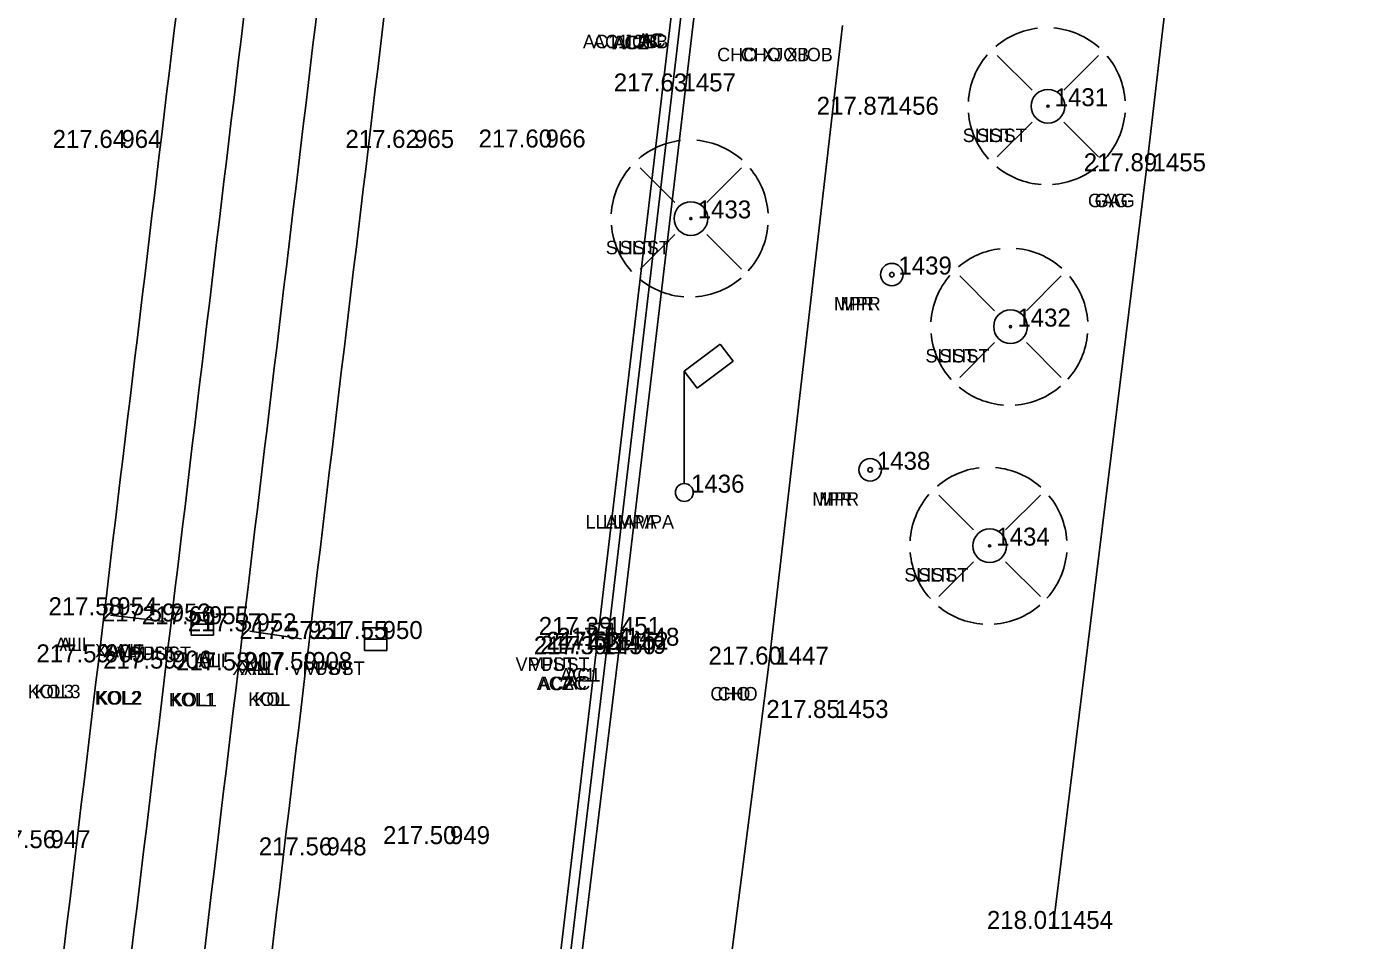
# Model space of a CAD drawing. Extents: x -471047 to -470889, y -1102859 to -1102000.
# Drawn here: x -470982.59 to -470952.73, y -1102585.27 to -1102564.92 of the extents above; entities that cross this region are included whole.
import ezdxf

# ---------------------------------------------------------------- set-up
doc = ezdxf.new("R2010")
doc.units = 0
for name, color, linetype in [('Vrstva 1', 7, 'Continuous'), ('Vrstva 16', 7, 'Continuous'), ('Vrstva 23', 7, 'Continuous'), ('Vrstva 24', 7, 'Continuous'), ('Vrstva 25', 7, 'Continuous'), ('Vrstva 29', 7, 'Continuous'), ('Vrstva 34', 7, 'Continuous'), ('Vrstva 35', 7, 'Continuous'), ('Vrstva 36', 7, 'Continuous'), ('Vrstva 38', 7, 'Continuous'), ('Vrstva 5', 7, 'Continuous'), ('Vrstva 6', 7, 'Continuous'), ('Vrstva 7', 7, 'Continuous'), ('Vrstva 8', 7, 'Continuous')]:
    doc.layers.add(name, color=color, linetype=linetype)

msp = doc.modelspace()

# ---------------------------------------------------------------- linework, layer by layer
at = {"layer": 'Vrstva 1'}
for points in [[(-471040.344, -1102858.385), (-471031.676, -1102846.187), (-471026.357, -1102838.629), (-471023.212, -1102833.975), (-471019.21, -1102827.465), (-471016.861, -1102823.272), (-471013.099, -1102815.912), (-471010.824, -1102810.955), (-471007.329, -1102802.292), (-471005.34, -1102796.515), (-471002.842, -1102787.838), (-471001.3, -1102780.997), (-471000.19, -1102774.713), (-470999.247, -1102768.204), (-470998.794, -1102764.784), (-470997.199, -1102751.812), (-470994.899, -1102732.807), (-470992.551, -1102713.262), (-470990.326, -1102694.887), (-470988.122, -1102676.57), (-470985.812, -1102657.305), (-470983.537, -1102638.407), (-470981.386, -1102620.622), (-470979.843, -1102608.014), (-470976.377, -1102579.253), (-470972.945, -1102550.69), (-470970.475, -1102530.206), (-470967.905, -1102508.801), (-470965.053, -1102485.131), (-470962.734, -1102465.9), (-470960.173, -1102444.812), (-470957.795, -1102425.103), (-470954.965, -1102401.839), (-470953.834, -1102392.574), (-470952.33, -1102379.985), (-470950.744, -1102366.853), (-470948.978, -1102352.106), (-470947.037, -1102335.844), (-470944.949, -1102318.462), (-470944.013, -1102310.745), (-470942.39, -1102297.267), (-470939.519, -1102273.45), (-470937.593, -1102257.43), (-470936.064, -1102244.81), (-470934.114, -1102228.634), (-470931.621, -1102207.856), (-470929.536, -1102190.857), (-470926.572, -1102166.31), (-470924.91, -1102152.663), (-470923.413, -1102140.333), (-470921.923, -1102127.669), (-470921.155, -1102120.084), (-470920.446, -1102109.574), (-470919.912, -1102099.137), (-470919.63, -1102088.981), (-470919.523, -1102081.193), (-470919.563, -1102070.395), (-470919.714, -1102064.236), (-470920.134, -1102054.704), (-470920.462, -1102047.615), (-470920.599, -1102044.52), (-470920.743, -1102041.873), (-470921.125, -1102034.455), (-470921.774, -1102030.337), (-470922.418, -1102027.787), (-470923.734, -1102023.93), (-470924.872, -1102021.434), (-470926.752, -1102018.182), (-470927.953, -1102016.45), (-470929.616, -1102014.424), (-470932.252, -1102011.756), (-470935.111, -1102009.425), (-470938.391, -1102007.371), (-470942.651, -1102005.401)], [(-471041.328, -1102857.18), (-471032.144, -1102844.242), (-471027.583, -1102837.763), (-471024.388, -1102833.028), (-471020.451, -1102826.6), (-471018.089, -1102822.378), (-471014.542, -1102815.445), (-471012.233, -1102810.418), (-471009.247, -1102803.108), (-471006.795, -1102796.098), (-471004.315, -1102787.532), (-471002.782, -1102780.723), (-471001.674, -1102774.458), (-471000.75, -1102768.095), (-471000.28, -1102764.601), (-470998.692, -1102751.741), (-470996.378, -1102732.635), (-470994.028, -1102713.058), (-470991.808, -1102694.749), (-470989.616, -1102676.447), (-470987.284, -1102657.013), (-470985.031, -1102638.272), (-470982.87, -1102620.431), (-470981.334, -1102607.933), (-470977.881, -1102579.263), (-470974.429, -1102550.492), (-470971.964, -1102530.054), (-470969.391, -1102508.607), (-470966.54, -1102484.984), (-470964.231, -1102465.853), (-470961.679, -1102444.752), (-470959.304, -1102425.078), (-470956.455, -1102401.634), (-470955.339, -1102392.489), (-470953.812, -1102379.71), (-470952.249, -1102366.808), (-470950.479, -1102352.023), (-470948.536, -1102335.868), (-470946.426, -1102318.233), (-470945.493, -1102310.531), (-470943.864, -1102297.013), (-470940.984, -1102273.071), (-470939.078, -1102257.195), (-470937.559, -1102244.684), (-470935.592, -1102228.353), (-470933.101, -1102207.653), (-470931.011, -1102190.57), (-470928.046, -1102166.021), (-470926.409, -1102152.578), (-470924.898, -1102140.121), (-470923.427, -1102127.544), (-470922.647, -1102119.826), (-470921.919, -1102109.229), (-470921.42, -1102099.134), (-470921.127, -1102089.016), (-470921.023, -1102081.453), (-470921.061, -1102070.468), (-470921.209, -1102064.314), (-470921.666, -1102053.966), (-470922.156, -1102043.345), (-470922.299, -1102039.934), (-470922.637, -1102034.36), (-470923.091, -1102031.241), (-470923.847, -1102028.247), (-470925.083, -1102024.594), (-470926.222, -1102022.086), (-470928.04, -1102018.943), (-470929.138, -1102017.357), (-470930.929, -1102015.175), (-470933.062, -1102013.049), (-470936.379, -1102010.368), (-470939.169, -1102008.662), (-470942.899, -1102006.906), (-470945.661, -1102005.908)], [(-471043.557, -1102855.955), (-471035.129, -1102844.026), (-471029.872, -1102836.499), (-471026.577, -1102831.578), (-471022.675, -1102825.415), (-471020.123, -1102821.053), (-471016.667, -1102814.59), (-471014.208, -1102809.45), (-471011.177, -1102802.451), (-471008.55, -1102795.333), (-471006.082, -1102787.209), (-471004.464, -1102780.376), (-471003.265, -1102774.167), (-471002.327, -1102767.948), (-471001.636, -1102762.527), (-471000.297, -1102751.605), (-470997.959, -1102732.524), (-470995.602, -1102712.802), (-470993.412, -1102694.623), (-470991.21, -1102676.17), (-470988.891, -1102656.857), (-470986.625, -1102638.083), (-470984.455, -1102620.195), (-470982.936, -1102607.733), (-470979.497, -1102579.223), (-470976.023, -1102550.279), (-470973.554, -1102529.822), (-470970.991, -1102508.497), (-470968.146, -1102484.787), (-470965.835, -1102465.72), (-470963.284, -1102444.529), (-470960.91, -1102424.942), (-470958.043, -1102401.343), (-470956.946, -1102392.356), (-470955.396, -1102379.408), (-470953.851, -1102366.636), (-470952.049, -1102351.733), (-470950.124, -1102335.611), (-470948.034, -1102318.083), (-470947.094, -1102310.328), (-470945.421, -1102296.51), (-470942.58, -1102272.848), (-470940.675, -1102256.948), (-470939.176, -1102244.526), (-470937.187, -1102228.174), (-470934.708, -1102207.467), (-470932.621, -1102190.433), (-470929.634, -1102165.778), (-470928.004, -1102152.415), (-470926.45, -1102139.595), (-470925.003, -1102127.418), (-470924.249, -1102119.695), (-470923.515, -1102109.093), (-470923.018, -1102099.069), (-470922.711, -1102088.911), (-470922.643, -1102081.356), (-470922.797, -1102070.414), (-470923.018, -1102064.454), (-470923.52, -1102053.203), (-470923.823, -1102047.529), (-470924.123, -1102041.506), (-470924.462, -1102037.486), (-470924.934, -1102031.904), (-470925.664, -1102028.672), (-470926.771, -1102025.506), (-470927.959, -1102022.914), (-470929.674, -1102020.028), (-470930.76, -1102018.498), (-470932.447, -1102016.478), (-470935.215, -1102013.816), (-470937.644, -1102011.98), (-470940.381, -1102010.371), (-470943.968, -1102008.669), (-470947.145, -1102007.524), (-470950.874, -1102006.74)], [(-471044.756, -1102855.056), (-471036.376, -1102843.177), (-471031.167, -1102835.741), (-471027.859, -1102830.8), (-471023.934, -1102824.593), (-471021.43, -1102820.312), (-471018.011, -1102813.91), (-471015.536, -1102808.75), (-471012.578, -1102801.897), (-471009.95, -1102794.77), (-471007.561, -1102786.914), (-471005.936, -1102780.074), (-471004.727, -1102773.818), (-471003.828, -1102767.827), (-471003.121, -1102762.345), (-471001.787, -1102751.467), (-470999.446, -1102732.348), (-470997.073, -1102712.539), (-470994.902, -1102694.521), (-470992.696, -1102676.023), (-470990.376, -1102656.68), (-470988.131, -1102638.071), (-470985.947, -1102620.018), (-470984.417, -1102607.512), (-470980.993, -1102579.08), (-470977.514, -1102550.137), (-470975.048, -1102529.649), (-470972.488, -1102508.37), (-470969.618, -1102484.508), (-470967.34, -1102465.669), (-470964.767, -1102444.39), (-470962.402, -1102424.781), (-470959.534, -1102401.193), (-470958.432, -1102392.151), (-470956.883, -1102379.208), (-470955.335, -1102366.424), (-470953.535, -1102351.506), (-470951.606, -1102335.399), (-470949.519, -1102317.94), (-470948.575, -1102310.159), (-470946.889, -1102296.144), (-470944.056, -1102272.618), (-470942.139, -1102256.659), (-470940.657, -1102244.341), (-470938.638, -1102227.749), (-470936.19, -1102207.298), (-470934.102, -1102190.255), (-470931.124, -1102165.639), (-470929.492, -1102152.254), (-470927.915, -1102139.252), (-470926.46, -1102127.103), (-470925.74, -1102119.604), (-470925.012, -1102108.913), (-470924.523, -1102099.054), (-470924.217, -1102088.866), (-470924.148, -1102081.334), (-470924.301, -1102070.391), (-470924.518, -1102064.43), (-470924.97, -1102054.435), (-470925.588, -1102041.569), (-470925.963, -1102035.313), (-470926.405, -1102032.225), (-470927.078, -1102029.198), (-470928.123, -1102026.148), (-470929.318, -1102023.558), (-470930.84, -1102020.97), (-470931.868, -1102019.515), (-470933.443, -1102017.605), (-470936.26, -1102014.885), (-470938.429, -1102013.255), (-470941.213, -1102011.639), (-470944.847, -1102009.927), (-470947.723, -1102008.912), (-470951.444, -1102008.161), (-470954.511, -1102007.931), (-470957.895, -1102008.041)]]:
    msp.add_spline(points, degree=3, dxfattribs=at)
at = {"layer": 'Vrstva 16'}
for p, q in [((-470960.196, -1102566.335), (-470960.972, -1102565.56)), ((-470959.486, -1102566.335), (-470958.712, -1102565.56)), ((-470960.196, -1102567.045), (-470960.972, -1102567.82)), ((-470959.486, -1102567.045), (-470958.712, -1102567.82)), ((-470968.15, -1102568.838), (-470968.926, -1102568.063)), ((-470967.44, -1102568.838), (-470966.666, -1102568.063)), ((-470968.15, -1102569.548), (-470968.926, -1102570.323)), ((-470967.44, -1102569.548), (-470966.666, -1102570.323)), ((-470961.03, -1102571.248), (-470961.806, -1102570.473)), ((-470960.32, -1102571.248), (-470959.546, -1102570.473)), ((-470961.03, -1102571.958), (-470961.806, -1102572.733)), ((-470960.32, -1102571.958), (-470959.546, -1102572.733)), ((-470961.496, -1102576.129), (-470962.27, -1102575.354)), ((-470960.786, -1102576.129), (-470960.01, -1102575.354)), ((-470961.496, -1102576.839), (-470962.27, -1102577.614)), ((-470960.786, -1102576.839), (-470960.01, -1102577.614))]:
    msp.add_line(p, q, dxfattribs=at)
for centre, radius in [((-470959.841, -1102566.69), 0.375), ((-470959.841, -1102566.69), 0.025), ((-470959.841, -1102566.69), 0.025), ((-470967.795, -1102569.193), 0.375), ((-470967.795, -1102569.193), 0.025), ((-470967.795, -1102569.193), 0.025), ((-470960.675, -1102571.603), 0.375), ((-470960.675, -1102571.603), 0.025), ((-470960.675, -1102571.603), 0.025), ((-470961.14, -1102576.484), 0.375), ((-470961.14, -1102576.484), 0.025), ((-470961.14, -1102576.484), 0.025)]:
    msp.add_circle(centre, radius, dxfattribs=at)
for centre, start, end in [((-470959.867, -1102566.69), 96.7144, 130.447), ((-470959.867, -1102566.69), 48.1897, 84.9117), ((-470959.867, -1102566.69), 139.23, 176.4602), ((-470959.867, -1102566.69), 3.8615, 39.6013), ((-470959.867, -1102566.69), 184.9408, 222.2827), ((-470959.867, -1102566.69), 318.1086, 355.0481), ((-470967.821, -1102569.193), 96.7144, 130.447), ((-470967.821, -1102569.193), 48.1897, 84.9117), ((-470967.821, -1102569.193), 139.23, 176.4602), ((-470967.821, -1102569.193), 3.8615, 39.6013), ((-470959.867, -1102566.69), 230.4703, 265.8356), ((-470959.867, -1102566.69), 274.1732, 310.7861), ((-470967.821, -1102569.193), 184.9408, 222.2827), ((-470967.821, -1102569.193), 318.1086, 355.0481), ((-470960.701, -1102571.603), 96.7144, 130.447), ((-470960.701, -1102571.603), 48.1897, 84.9117), ((-470967.821, -1102569.193), 230.4703, 265.8356), ((-470967.821, -1102569.193), 274.1732, 310.7861), ((-470960.701, -1102571.603), 139.23, 176.4602), ((-470960.701, -1102571.603), 3.8615, 39.6013), ((-470960.701, -1102571.603), 184.9408, 222.2827), ((-470960.701, -1102571.603), 318.1086, 355.0481), ((-470960.701, -1102571.603), 230.4703, 265.8356), ((-470960.701, -1102571.603), 274.1732, 310.7861), ((-470961.166, -1102576.484), 96.7144, 130.447), ((-470961.166, -1102576.484), 48.1897, 84.9117), ((-470961.166, -1102576.484), 139.23, 176.4602), ((-470961.166, -1102576.484), 3.8615, 39.6013), ((-470961.166, -1102576.484), 184.9408, 222.2827), ((-470961.166, -1102576.484), 318.1086, 355.0481), ((-470961.166, -1102576.484), 274.1732, 310.7861), ((-470961.166, -1102576.484), 230.4703, 265.8356)]:
    msp.add_arc(centre, 1.75, start, end, dxfattribs=at)
at = {"layer": 'Vrstva 23'}
for p, q in [((-470967.146, -1102571.991), (-470967.941, -1102572.596)), ((-470966.856, -1102572.368), (-470967.146, -1102571.991)), ((-470967.654, -1102572.974), (-470966.856, -1102572.368)), ((-470967.941, -1102572.596), (-470967.941, -1102575.096)), ((-470967.941, -1102572.596), (-470967.654, -1102572.974))]:
    msp.add_line(p, q, dxfattribs=at)
msp.add_circle((-470967.941, -1102575.296), 0.2, dxfattribs=at)
at = {"layer": 'Vrstva 24'}
for centre, radius in [((-470963.319, -1102570.442), 0.25), ((-470963.319, -1102570.442), 0.05), ((-470963.801, -1102574.792), 0.25), ((-470963.801, -1102574.792), 0.05)]:
    msp.add_circle(centre, radius, dxfattribs=at)
at = {"layer": 'Vrstva 25'}
for p, q in [((-470978.929, -1102577.978), (-470978.929, -1102578.478)), ((-470978.429, -1102577.978), (-470978.929, -1102577.978)), ((-470978.429, -1102578.478), (-470978.429, -1102577.978)), ((-470978.929, -1102578.228), (-470978.429, -1102578.228)), ((-470975.064, -1102578.313), (-470975.064, -1102578.813)), ((-470974.564, -1102578.313), (-470975.064, -1102578.313)), ((-470974.564, -1102578.813), (-470974.564, -1102578.313)), ((-470970.051, -1102578.218), (-470970.051, -1102578.718)), ((-470969.551, -1102578.218), (-470970.051, -1102578.218)), ((-470969.551, -1102578.718), (-470969.551, -1102578.218)), ((-470978.929, -1102578.478), (-470978.429, -1102578.478)), ((-470975.064, -1102578.563), (-470974.564, -1102578.563)), ((-470970.051, -1102578.468), (-470969.551, -1102578.468)), ((-470970.051, -1102578.718), (-470969.551, -1102578.718)), ((-470975.064, -1102578.813), (-470974.564, -1102578.813))]:
    msp.add_line(p, q, dxfattribs=at)
at = {"layer": 'Vrstva 29'}
for p, q in [((-470979.525, -1102578.168), (-470980.721, -1102578.028)), ((-470976.472, -1102578.56), (-470977.621, -1102578.388))]:
    msp.add_line(p, q, dxfattribs=at)
at = {"layer": 'Vrstva 34'}
for p, q in [((-470968.13, -1102566.36), (-470968.13, -1102566.36)), ((-470959.84, -1102566.69), (-470959.84, -1102566.69)), ((-470963.61, -1102566.88), (-470963.61, -1102566.88)), ((-470980.63, -1102567.62), (-470980.63, -1102567.62)), ((-470974.11, -1102567.62), (-470974.11, -1102567.62)), ((-470971.18, -1102567.61), (-470971.18, -1102567.61)), ((-470957.66, -1102568.14), (-470957.66, -1102568.14)), ((-470967.79, -1102569.19), (-470967.79, -1102569.19)), ((-470963.32, -1102570.44), (-470963.32, -1102570.44)), ((-470960.67, -1102571.6), (-470960.67, -1102571.6)), ((-470963.8, -1102574.79), (-470963.8, -1102574.79)), ((-470967.94, -1102575.3), (-470967.94, -1102575.3)), ((-470961.14, -1102576.48), (-470961.14, -1102576.48)), ((-470980.72, -1102578.03), (-470980.72, -1102578.03)), ((-470979.53, -1102578.17), (-470979.53, -1102578.17)), ((-470978.68, -1102578.23), (-470978.68, -1102578.23)), ((-470977.62, -1102578.39), (-470977.62, -1102578.39)), ((-470976.47, -1102578.56), (-470976.47, -1102578.56)), ((-470974.81, -1102578.56), (-470974.81, -1102578.56)), ((-470969.8, -1102578.47), (-470969.8, -1102578.47)), ((-470969.39, -1102578.71), (-470969.39, -1102578.71)), ((-470969.91, -1102578.9), (-470969.91, -1102578.9)), ((-470969.68, -1102578.89), (-470969.68, -1102578.89)), ((-470969.63, -1102578.8), (-470969.63, -1102578.8)), ((-470980.99, -1102579.08), (-470980.99, -1102579.08)), ((-470979.5, -1102579.22), (-470979.5, -1102579.22)), ((-470977.88, -1102579.26), (-470977.88, -1102579.26)), ((-470976.38, -1102579.25), (-470976.38, -1102579.25)), ((-470966.06, -1102579.13), (-470966.06, -1102579.13)), ((-470964.73, -1102580.32), (-470964.73, -1102580.32)), ((-470973.31, -1102583.13), (-470973.31, -1102583.13)), ((-470982.21, -1102583.22), (-470982.21, -1102583.22)), ((-470976.06, -1102583.38), (-470976.06, -1102583.38)), ((-470959.73, -1102585.02), (-470959.73, -1102585.02))]:
    msp.add_line(p, q, dxfattribs=at)
at = {"layer": 'Vrstva 5'}
for p, q in [((-470969.913, -1102578.903), (-470968.23, -1102564.623)), ((-470971.196, -1102589.753), (-470969.913, -1102578.903))]:
    msp.add_line(p, q, dxfattribs=at)
at = {"layer": 'Vrstva 6'}
for p, q in [((-470956.273, -1102556.258), (-470957.656, -1102568.144)), ((-470957.656, -1102568.144), (-470959.734, -1102585.018))]:
    msp.add_line(p, q, dxfattribs=at)
at = {"layer": 'Vrstva 7'}
for p, q in [((-470969.386, -1102578.705), (-470967.713, -1102564.6)), ((-470970.734, -1102589.803), (-470969.386, -1102578.705))]:
    msp.add_line(p, q, dxfattribs=at)
at = {"layer": 'Vrstva 8'}
for p, q in [((-470969.682, -1102578.891), (-470968.004, -1102564.574)), ((-470966.057, -1102579.132), (-470964.419, -1102564.89)), ((-470970.974, -1102589.772), (-470969.682, -1102578.891)), ((-470967.658, -1102591.567), (-470966.057, -1102579.132))]:
    msp.add_line(p, q, dxfattribs=at)

# ---------------------------------------------------------------- texts
at = {"layer": 'Vrstva 35'}
for s, p in [('AC1 JOB', (-470970.199, -1102565.4)), ('AC1 JOB', (-470969.974, -1102565.4)), ('AC2', (-470969.546, -1102565.42)), ('AC2', (-470969.505, -1102565.42)), ('AC', (-470968.989, -1102565.37)), ('AC', (-470968.914, -1102565.37)), ('CHO XJOB', (-470967.209, -1102565.69)), ('CHO XJOB', (-470966.684, -1102565.69)), ('SLIST', (-470961.74, -1102567.49)), ('SLIST', (-470961.429, -1102567.49)), ('GAG', (-470958.95, -1102568.94)), ('GAG', (-470958.799, -1102568.94)), ('SLIST', (-470969.69, -1102569.99)), ('SLIST', (-470969.379, -1102569.99)), ('MPR', (-470964.609, -1102571.24)), ('MPR', (-470964.459, -1102571.24)), ('SLIST', (-470962.57, -1102572.4)), ('SLIST', (-470962.259, -1102572.4)), ('MPR', (-470965.089, -1102575.59)), ('MPR', (-470964.939, -1102575.59)), ('LLAMPA', (-470970.14, -1102576.1)), ('LLAMPA', (-470969.754, -1102576.1)), ('SLIST', (-470963.04, -1102577.28)), ('SLIST', (-470962.729, -1102577.28)), ('ALI', (-470981.958, -1102578.83)), ('ALI', (-470981.859, -1102578.83)), ('XALI', (-470981.068, -1102578.97)), ('XALI', (-470980.894, -1102578.97)), ('VPUST', (-470980.58, -1102579.03)), ('VPUST', (-470980.269, -1102579.03)), ('ALI', (-470978.858, -1102579.19)), ('ALI', (-470978.759, -1102579.19)), ('VPUST', (-470971.7, -1102579.27)), ('VPUST', (-470971.389, -1102579.27)), ('XALI', (-470978.008, -1102579.36)), ('XALI', (-470977.834, -1102579.36)), ('VPUST', (-470976.71, -1102579.36)), ('VPUST', (-470976.399, -1102579.36)), ('AC1', (-470970.707, -1102579.51)), ('AC1', (-470970.59, -1102579.51)), ('KOL3', (-470982.565, -1102579.88)), ('KOL3', (-470982.418, -1102579.88)), ('AC2', (-470971.226, -1102579.7)), ('AC2', (-470971.185, -1102579.7)), ('AC', (-470970.669, -1102579.69)), ('AC', (-470970.594, -1102579.69)), ('KOL2', (-470981.075, -1102580.02)), ('KOL2', (-470981.041, -1102580.02)), ('KOL1', (-470979.422, -1102580.06)), ('KOL1', (-470979.38, -1102580.06)), ('KOL', (-470977.655, -1102580.05)), ('KOL', (-470977.519, -1102580.05)), ('CHO', (-470967.361, -1102579.93)), ('CHO', (-470967.199, -1102579.93))]:
    msp.add_text(s, height=0.3, dxfattribs=at).set_placement(p)
at = {"layer": 'Vrstva 36'}
for s, p in [(' 1457', (-470968.13, -1102566.36)), (' 1456', (-470963.61, -1102566.88)), (' 1431', (-470959.84, -1102566.69)), (' 964', (-470980.63, -1102567.62)), (' 965', (-470974.11, -1102567.62)), (' 966', (-470971.18, -1102567.61)), (' 1455', (-470957.66, -1102568.14)), (' 1433', (-470967.79, -1102569.19)), (' 1439', (-470963.32, -1102570.44)), (' 1432', (-470960.67, -1102571.6)), (' 1438', (-470963.8, -1102574.79)), (' 1436', (-470967.94, -1102575.3)), (' 1434', (-470961.14, -1102576.48)), (' 954', (-470980.72, -1102578.03)), (' 953', (-470979.53, -1102578.17)), (' 955', (-470978.68, -1102578.23)), (' 952', (-470977.62, -1102578.39)), (' 1451', (-470969.8, -1102578.47)), (' 951', (-470976.47, -1102578.56)), (' 950', (-470974.81, -1102578.56)), (' 1452', (-470969.63, -1102578.8)), (' 1448', (-470969.39, -1102578.71)), (' 905', (-470980.99, -1102579.08)), (' 1450', (-470969.91, -1102578.9)), (' 1449', (-470969.68, -1102578.89)), (' 906', (-470979.5, -1102579.22)), (' 907', (-470977.88, -1102579.26)), (' 908', (-470976.38, -1102579.25)), (' 1447', (-470966.06, -1102579.13)), (' 1453', (-470964.73, -1102580.32)), (' 947', (-470982.21, -1102583.22)), (' 949', (-470973.31, -1102583.13)), (' 948', (-470976.06, -1102583.38)), (' 1454', (-470959.73, -1102585.02))]:
    msp.add_text(s, height=0.4, dxfattribs=at).set_placement(p)
at = {"layer": 'Vrstva 38'}
for s, p in [('217.63 ', (-470969.513, -1102566.36)), ('217.87 ', (-470964.993, -1102566.88)), ('217.64 ', (-470982.012, -1102567.62)), ('217.62 ', (-470975.491, -1102567.62)), ('217.60 ', (-470972.523, -1102567.61)), ('217.89 ', (-470959.044, -1102568.14)), ('217.58 ', (-470982.104, -1102578.03)), ('217.59 ', (-470980.914, -1102578.17)), ('217.60 ', (-470980.023, -1102578.23)), ('217.57 ', (-470979.003, -1102578.39)), ('217.39 ', (-470971.184, -1102578.47)), ('217.57 ', (-470977.853, -1102578.56)), ('217.55 ', (-470976.194, -1102578.56)), ('217.53 ', (-470971.013, -1102578.8)), ('217.54 ', (-470970.772, -1102578.71)), ('217.59 ', (-470982.374, -1102579.08)), ('217.39 ', (-470971.294, -1102578.9)), ('217.41 ', (-470971.15, -1102578.89)), ('217.60 ', (-470967.403, -1102579.13)), ('217.59 ', (-470980.884, -1102579.22)), ('217.58 ', (-470979.264, -1102579.26)), ('217.59 ', (-470977.764, -1102579.25)), ('217.85 ', (-470966.114, -1102580.32)), ('217.56 ', (-470983.57, -1102583.22)), ('217.50 ', (-470974.653, -1102583.13)), ('217.56 ', (-470977.42, -1102583.38)), ('218.01 ', (-470961.2, -1102585.02))]:
    msp.add_text(s, height=0.4, dxfattribs=at).set_placement(p)

doc.saveas('drawing.dxf')
